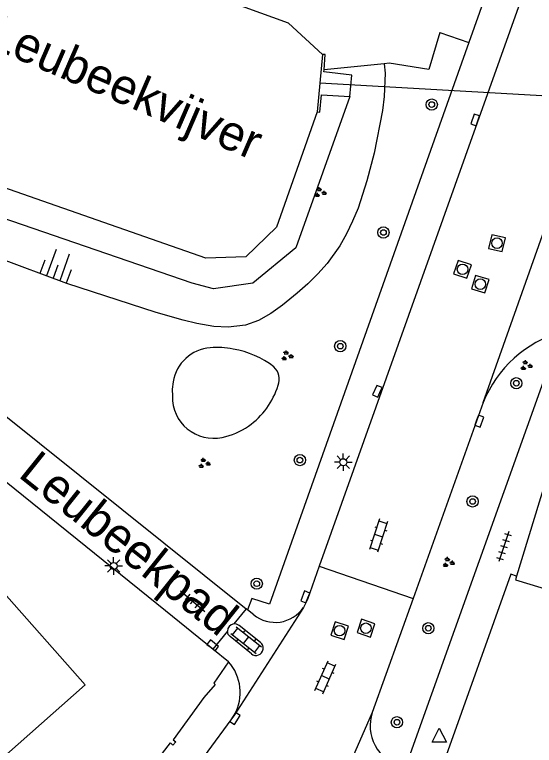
# Model space of a CAD drawing. Extents: x 131000 to 133013, y 393000 to 396501.
# Drawn here: x 131206.4 to 131243.4, y 394975.6 to 395027.6 of the extents above; entities that cross this region are included whole.
import ezdxf

# ---------------------------------------------------------------- set-up
doc = ezdxf.new("R2010")
doc.units = 0
for name, color, linetype in [('gg-afsc-erfafscheiding', 7, 'Continuous'), ('gg-anno-naam water', 7, 'Continuous'), ('gg-anno-openbare ruimte label', 7, 'Continuous'), ('gg-bbg-gedigitaliseerde bebouwing', 7, 'Continuous'), ('gg-bbg-hoofdgebouw', 7, 'Continuous'), ('gg-knt-BGT kruinlijn', 7, 'Continuous'), ('gg-knt-verharding', 7, 'Continuous'), ('gg-knt-verharding nz', 7, 'Continuous'), ('gg-kntw-beschoeiing', 7, 'Continuous'), ('gg-kwrk-duiker nz buis', 7, 'Continuous'), ('gg-kwrk-uitstroombak niveau min 01', 7, 'Continuous'), ('gt-grn-groengrens', 7, 'Continuous'), ('gt-grn-vlakafsluiter', 7, 'Continuous'), ('gt-grn-weggrens', 7, 'Continuous'), ('gt-symb-boom', 7, 'Continuous'), ('gt-symb-groenvak', 7, 'Continuous'), ('gt-symb-klinker verharding', 7, 'Continuous'), ('gt-symb-kolk', 7, 'Continuous'), ('gt-symb-lichtmast', 7, 'Continuous'), ('gt-symb-rioolschacht', 7, 'Continuous'), ('gt-symb-talud symbool', 7, 'Continuous'), ('gt-symb-tegel verharding', 7, 'Continuous'), ('gt-symb-waterafsluiter', 7, 'Continuous'), ('gx-grn-maaiveld', 7, 'Continuous')]:
    doc.layers.add(name, color=color, linetype=linetype)

# ---------------------------------------------------------------- blocks, each defined once
blk = doc.blocks.new('gt0-GRVAK')
at = {"layer": 'gt-symb-groenvak'}
for p, q in [((-0.11, 0.189), (-0.228, 0.24)), ((-0.182, 0.153), (0.088, 0.153)), ((-0.091, 0.211), (-0.156, 0.322)), ((-0.047, 0.214), (-0.047, 0.393)), ((-0.004, 0.211), (0.061, 0.322)), ((0.015, 0.189), (0.133, 0.24)), ((0.262, -0.052), (0.197, 0.059)), ((0.305, -0.049), (0.305, 0.13)), ((0.349, -0.052), (0.414, 0.059)), ((-0.245, -0.228), (-0.363, -0.177)), ((-0.318, -0.264), (-0.047, -0.264)), ((-0.226, -0.206), (-0.291, -0.095)), ((-0.183, -0.203), (-0.183, -0.024)), ((-0.139, -0.206), (-0.074, -0.095)), ((-0.12, -0.228), (-0.002, -0.177)), ((0.243, -0.074), (0.125, -0.023)), ((0.17, -0.11), (0.441, -0.11)), ((0.368, -0.074), (0.486, -0.023))]:
    blk.add_line(p, q, dxfattribs=at)
blk = doc.blocks.new('gt0-RS')
at = {"layer": 'gt-symb-rioolschacht'}
blk.add_lwpolyline([(-0.5, -0.5), (0.5, -0.5), (0.5, 0.5), (-0.5, 0.5)], close=True, dxfattribs=at)
blk.add_circle((0, 0), 0.375, dxfattribs=at)
blk = doc.blocks.new('gt0-KOLK')
at = {"layer": 'gt-symb-kolk'}
blk.add_lwpolyline([(0, 0), (0.375, 0), (0.375, 0.4), (-0.375, 0.4), (-0.375, 0), (0, 0)], dxfattribs=at)
blk = doc.blocks.new('gt0-BOOM')
at = {"layer": 'gt-symb-boom'}
for radius in [0.4, 0.2]:
    blk.add_circle((0, 0), radius, dxfattribs=at)
blk = doc.blocks.new('gt0-LMAST')
at = {"layer": 'gt-symb-lichtmast'}
for p, q in [((-0.005, 0.246), (-0.005, 0.621)), ((-0.182, 0.173), (-0.447, 0.438)), ((0.172, 0.173), (0.437, 0.438)), ((-0.255, -0.004), (-0.63, -0.004)), ((-0.182, -0.181), (-0.447, -0.446)), ((-0.005, -0.254), (-0.005, -0.629)), ((0.437, -0.446), (0.172, -0.181)), ((0.245, -0.004), (0.62, -0.004))]:
    blk.add_line(p, q, dxfattribs=at)
blk.add_circle((-0.005, -0.004), 0.25, dxfattribs=at)
blk = doc.blocks.new('gt0-TALUD_1')
at = {"layer": 'gt-symb-talud symbool'}
for p, q in [((-1, -1), (-1, 0)), ((-0.5, -2), (-0.5, 0)), ((0, -1), (0, 0)), ((0.5, -2), (0.5, 0)), ((1, -1), (1, 0))]:
    blk.add_line(p, q, dxfattribs=at)
blk = doc.blocks.new('gt0-TEG1')
at = {"layer": 'gt-symb-tegel verharding'}
for p, q in [((-1.125, 0), (1.125, 0)), ((-0.9, -0.25), (-0.9, 0.25)), ((-0.45, -0.25), (-0.45, 0.25)), ((0, -0.25), (0, 0.25)), ((0.45, -0.25), (0.45, 0.25)), ((0.9, -0.25), (0.9, 0.25))]:
    blk.add_line(p, q, dxfattribs=at)
blk = doc.blocks.new('gt0-KL1')
at = {"layer": 'gt-symb-klinker verharding'}
for p, q in [((-1.15, 0.3), (1.15, 0.3)), ((-1, -0.3), (-1, 0.3)), ((-0.5, 0.3), (-0.5, 0.45)), ((0, -0.3), (0, 0.3)), ((0.5, 0.3), (0.5, 0.45)), ((1, -0.3), (1, 0.3)), ((-1.15, -0.3), (1.15, -0.3)), ((-0.5, -0.45), (-0.5, -0.3)), ((0.5, -0.45), (0.5, -0.3))]:
    blk.add_line(p, q, dxfattribs=at)
blk = doc.blocks.new('gt0-WAFSL')
at = {"layer": 'gt-symb-waterafsluiter'}
for p, q in [((-0.5, -0.333), (0, 0.667)), ((0, 0.667), (0.5, -0.333)), ((0.5, -0.333), (-0.5, -0.333))]:
    blk.add_line(p, q, dxfattribs=at)

msp = doc.modelspace()

# ---------------------------------------------------------------- linework, layer by layer
at = {"layer": 'gg-afsc-erfafscheiding'}
msp.add_line((131232.715, 395024.084), (131228.442, 395023.641), dxfattribs=at)
for points in [[(131236.676, 395026.307), (131235.882, 395023.685), (131233.07, 395024.121), (131232.715, 395024.084)], [(131217.168, 394985.172), (131198.811, 395000), (131191.145, 395006.246)]]:
    msp.add_lwpolyline(points, dxfattribs=at)
at = {"layer": 'gg-bbg-gedigitaliseerde bebouwing'}
msp.add_line((131242.038, 394987.371), (131247.42, 394985.744), dxfattribs=at)
at = {"layer": 'gg-bbg-hoofdgebouw'}
for p, q in [((131244.668, 394996), (131242.119, 394987.636)), ((131242.119, 394987.636), (131242.038, 394987.371))]:
    msp.add_line(p, q, dxfattribs=at)
msp.add_lwpolyline([(131205.518, 394986.641), (131211.453, 394979.91), (131204.405, 394973.675), (131205.071, 394972.955), (131200.426, 394968.848)], dxfattribs=at)
at = {"layer": 'gg-knt-BGT kruinlijn'}
msp.add_lwpolyline([(131232.715, 395024.084), (131232.777, 395023.412), (131232.725, 395021.752), (131232.6, 395020.761), (131231.993, 395017.733), (131231.488, 395015.751), (131230.854, 395013.823), (131230.473, 395012.894), (131230.041, 395011.997), (131229.552, 395011.138), (131228.653, 395009.881), (131227.996, 395009.139), (131227.285, 395008.437), (131226.529, 395007.766), (131225.486, 395006.923), (131224.656, 395006.325), (131223.783, 395005.826), (131222.856, 395005.488), (131221.621, 395005.349), (131220.609, 395005.408), (131219.394, 395005.607), (131218.421, 395005.837), (131216.507, 395006.388), (131210.167, 395008.465), (131205.191, 395010.304)], dxfattribs=at)
at = {"layer": 'gg-knt-verharding'}
for p, q in [((131248.202, 395052.346), (131238.723, 395025.601)), ((131250.541, 395051.401), (131228.103, 394988.341)), ((131193.339, 395009.017), (131222.895, 394985.319)), ((131234.228, 394974.029), (131245.283, 395005.017)), ((131239.746, 395000), (131234.773, 394986.063)), ((131228.103, 394988.341), (131234.773, 394986.063)), ((131234.773, 394986.063), (131231.872, 394977.934)), ((131220.545, 394982.445), (131217.168, 394985.172)), ((131222.895, 394985.319), (131222.019, 394984.239)), ((131223, 394985.237), (131222.895, 394985.319)), ((131223.44, 394984.893), (131223, 394985.237)), ((131221.573, 394983.73), (131220.545, 394982.445)), ((131221.647, 394981.554), (131220.545, 394982.445))]:
    msp.add_line(p, q, dxfattribs=at)
for points in [[(131238.723, 395025.601), (131224.558, 394985.638), (131223.302, 394986.05), (131223, 394985.237)], [(131228.103, 394988.341), (131227.259, 394985.969), (131226.972, 394985.407)], [(131242.119, 394987.636), (131241.706, 394987.772), (131237.007, 394974.55)], [(131223.921, 394982.927), (131222.401, 394984.132), (131222.219, 394984.225), (131222.019, 394984.239)], [(131221.647, 394981.554), (131220.614, 394980.025), (131220.703, 394979.937), (131219.894, 394979.02), (131217.723, 394976.012), (131217.91, 394975.857), (131217.692, 394975.62), (131217.524, 394975.78)], [(131222.07, 394977.79), (131219.92, 394974.841), (131218.014, 394972.393)]]:
    msp.add_lwpolyline(points, dxfattribs=at)
for centre, radius, start, end in [((131247.774, 394996.704), 8.678, 106.6804, 157.6782), ((131224.968, 394986.784), 2.431, 231.0579, 325.502), ((131222.082, 394983.734), 0.509, 97.0849, 180.4636), ((131223.599, 394982.52), 0.519, 231.1683, 51.6498), ((131219.221, 394979.376), 3.261, 330.9065, 41.9175), ((131234.687, 394976.99), 2.969, 161.463, 254.3703), ((131167.544, 395014.116), 62.989, 295.60652, 322.51121)]:
    msp.add_arc(centre, radius, start, end, dxfattribs=at)
at = {"layer": 'gg-knt-verharding nz'}
for p, q in [((131226.972, 394985.407), (131222.07, 394977.79)), ((131231.872, 394977.934), (131228.381, 394970.023))]:
    msp.add_line(p, q, dxfattribs=at)
at = {"layer": 'gg-kntw-beschoeiing'}
for points in [[(131228.327, 395024.752), (131225.913, 395026.961), (131208.807, 395033.186)], [(131227.951, 395020.665), (131225.066, 395012.454), (131222.876, 395010.354), (131220.032, 395010.267), (131199.763, 395017.353), (131193.008, 395016.817), (131189.403, 395012.329)]]:
    msp.add_lwpolyline(points, dxfattribs=at)
at = {"layer": 'gg-kwrk-duiker nz buis'}
msp.add_lwpolyline([(131263.49, 395020.074), (131261.392, 395020.815), (131228.139, 395022.709)], dxfattribs=at)
at = {"layer": 'gg-kwrk-uitstroombak niveau min 01'}
msp.add_line((131228.327, 395024.752), (131227.951, 395020.665), dxfattribs=at)
for points in [[(131228.442, 395023.641), (131228.517, 395024.735), (131228.327, 395024.752)], [(131230.282, 395021.753), (131230.421, 395023.278), (131228.433, 395023.502), (131228.442, 395023.641)], [(131227.951, 395020.665), (131228.145, 395020.642), (131228.269, 395021.88), (131230.282, 395021.753)]]:
    msp.add_lwpolyline(points, dxfattribs=at)
at = {"layer": 'gt-grn-groengrens'}
for points in [[(131230.282, 395021.753), (131226.441, 395011.001), (131223.385, 395008.469), (131220.594, 395008.081), (131219.064, 395008.467), (131199.405, 395015.225), (131193.858, 395014.878), (131190.858, 395011.174)], [(131217.72, 395001.458), (131217.656, 395000.946), (131217.658, 395000.435)]]:
    msp.add_lwpolyline(points, dxfattribs=at)
for centre, radius, start, end in [((131220.565, 395001.008), 2.88, 94.277, 171.0077), ((131220.872, 394998.415), 5.49, 78.3627, 95.4529), ((131220.924, 394997.427), 6.451, 52.1987, 80.5861), ((131224.054, 395001.652), 1.201, 338.6516, 46.6468), ((131219.925, 395002.801), 5.482, 305.0387, 343.1794), ((131220.581, 395000.37), 2.923, 178.722, 282.2515), ((131220.294, 395002.222), 4.795, 280.9003, 305.4008)]:
    msp.add_arc(centre, radius, start, end, dxfattribs=at)
at = {"layer": 'gt-grn-vlakafsluiter'}
msp.add_line((131236.676, 395026.307), (131238.723, 395025.601), dxfattribs=at)
at = {"layer": 'gt-grn-weggrens'}
msp.add_line((131239.746, 395000), (131246.619, 395019.403), dxfattribs=at)
at = {"layer": 'gx-grn-maaiveld'}
msp.add_lwpolyline([(131223.273, 394982.115), (131221.76, 394983.339), (131221.632, 394983.495), (131221.573, 394983.73)], dxfattribs=at)

# ---------------------------------------------------------------- block references
at = {"layer": 'gt-symb-boom'}
for p in [(131236.095, 395021.182), (131232.662, 395012.082), (131229.595, 395003.997), (131242.106, 395001.363), (131226.722, 394995.895), (131239, 394992.952), (131223.658, 394987.106), (131235.852, 394983.938), (131233.622, 394977.255)]:
    msp.add_blockref('gt0-BOOM', p, dxfattribs=at)
at = {"layer": 'gt-symb-groenvak'}
for p in [(131228.15, 395014.919), (131225.797, 395003.302), (131242.797, 395002.618), (131219.905, 394995.663), (131237.26, 394988.613)]:
    msp.add_blockref('gt0-GRVAK', p, dxfattribs=at)
at = {"layer": 'gt-symb-klinker verharding'}
for p, rotation in [((131232.315, 394990.533), -107.81888891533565), ((131222.912, 394983.092), -38.38245733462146), ((131228.537, 394980.443), 66.04914468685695)]:
    msp.add_blockref('gt0-KL1', p, dxfattribs=dict(at, rotation=rotation))
at = {"layer": 'gt-symb-kolk'}
for p, rotation in [((131239.37, 395020.021), 70.55043123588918), ((131232.408, 395000.705), 65.8688747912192), ((131239.285, 394998.734), -109.57672556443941), ((131227.29, 394986.089), 68.10284941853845), ((131220.406, 394982.556), -38.543462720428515), ((131221.942, 394977.624), -123.16559931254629)]:
    msp.add_blockref('gt0-KOLK', p, dxfattribs=dict(at, rotation=rotation))
at = {"layer": 'gt-symb-lichtmast'}
for p in [(131229.81, 394995.749), (131213.492, 394988.369)]:
    msp.add_blockref('gt0-LMAST', p, dxfattribs=at)
at = {"layer": 'gt-symb-rioolschacht'}
for p, rotation in [((131240.735, 395011.322), 76.58892815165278), ((131238.283, 395009.465), 71.45633066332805), ((131239.545, 395008.406), 73.26783977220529), ((131231.417, 394983.939), 71.45633066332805), ((131229.546, 394983.764), 71.45633066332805)]:
    msp.add_blockref('gt0-RS', p, dxfattribs=dict(at, rotation=rotation))
at = {"layer": 'gt-symb-talud symbool', "xscale": 0.9996849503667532, "yscale": 0.9996849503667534, "rotation": 159.93365037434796}
msp.add_blockref('gt0-TALUD_1', (131209.181, 395008.826), dxfattribs=at)
at = {"layer": 'gt-symb-tegel verharding'}
for p, rotation in [((131241.218, 394989.752), -108.48932632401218), ((131219.107, 394985.867), -40.33396601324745)]:
    msp.add_blockref('gt0-TEG1', p, dxfattribs=dict(at, rotation=rotation))
at = {"layer": 'gt-symb-waterafsluiter'}
msp.add_blockref('gt0-WAFSL', (131236.633, 394976.164), dxfattribs=at)

# ---------------------------------------------------------------- texts
at = {"layer": 'gg-anno-naam water'}
msp.add_text('Leubeekvijver', height=2.5, rotation=336.666, dxfattribs=at).set_placement((131204.409, 395025.373))
at = {"layer": 'gg-anno-openbare ruimte label'}
msp.add_text('Leubeekpad', height=2.5, rotation=321.3, dxfattribs=at).set_placement((131206.624, 394994.766))

doc.saveas('drawing.dxf')
